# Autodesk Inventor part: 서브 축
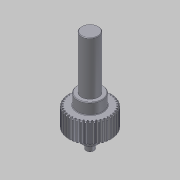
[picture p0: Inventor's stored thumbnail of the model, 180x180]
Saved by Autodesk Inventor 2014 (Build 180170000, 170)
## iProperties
Created: 2013-12
Part Number: 서브 축
Material: 강
Document SubType Name: Modeling
Designer: 한국산업디자인학원
Categories: <?xml version="1.0" encoding="UTF-16"?> <MemberInstance><Categories><FamilyTemplate><FamilyTemplateParameter ValueType="xs:double" Id="1" ObjectReferenceKey="da
Density: 1 g/cm^3
Appearance: 강철
CustomPartVersion: 1
Author: 한국산업디자인학원
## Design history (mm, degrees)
sketch "Sketch1"
  geometry: C1 r 21 at (0, 0)
  constraints: 1 centre point
  dimensions: "d0" = 42 diameter of C1 (= da_da)
extrude "Extrusion1" new body sketch "Sketch1" distance "d1" = 20 (= da_b); taper "d2" = 0 deg
workplane "Work Plane2"
feature "피치 지름" dims "d4" = 10, "d5" = 0
workplane "Work Plane8"
workplane "Work Plane9"
chamfer "모따기1" distance "d49" = 1; stored, may be unused: second distance "d50" = 2, angle "d51" = 45 deg
sketch "스케치3"
  geometry: C1 r 12.5 at (0, 0); 1 further point
  constraints: 1 centre point, 1 coincident
  dimensions: "d52" = 25 diameter of C1
extrude "돌출2" join sketch "스케치3" distance "d53" = 11; taper "d54" = 0 deg
sketch "스케치4"
  geometry: C1 r 8.5 at (0, 0); 1 further point
  constraints: 1 centre point, 1 coincident
  dimensions: "d55" = 17 diameter of C1
extrude "돌출3" join sketch "스케치4" distance "d56" = 53; taper "d57" = 0 deg
sketch "스케치5"
  geometry: C1 r 7.5 at (0, 0); 1 further point
  constraints: 1 centre point, 1 coincident
  dimensions: "d62" = 15 diameter of C1
extrude "돌출4" join sketch "스케치5" distance "d63" = 11; taper "d64" = 0 deg
sketch "스케치6"
  geometry: C1 r 4 at (0, 0); 1 further point
  constraints: 1 centre point, 1 coincident
  dimensions: "d65" = 8 diameter of C1
extrude "돌출5" join sketch "스케치6" distance "d66" = 7; taper "d67" = 0 deg
chamfer "모따기2" distance "d58" = 0.5; stored, may be unused: second distance "d59" = 2, angle "d60" = 45 deg
fillet "모깎기1" dims "d61" = 0.5
feature "스퍼 기어" dims "da_b" = 20, "da_d" = 40, "da_aw" = 31, "da_da" = 42, "da_df" = 37.5, "da_dw" = 40, angle "da_beta" = 0 deg, "da_lefttooth" = 0, "da_righttooth" = 0
body "Solid1"
sketch "Sketch2"
  geometry: C1 r 21 at (0, 0) reference; C2 r 20 at (0, 0)
  constraints: 1 centre point, 1 coincident
  dimensions: "d3" = 40 diameter of C2 (= da_dw)
body "Srf1"
other parameters: "d16" = 31 (= da_aw), "d17" = 0, "d34" = 4.5 deg (computed from da_z), "d39" = 0, "d41" = 0, "d43" = 31 (= da_aw), "d46" = 31 (= da_aw), "d47" = 0, "d48" = 0
